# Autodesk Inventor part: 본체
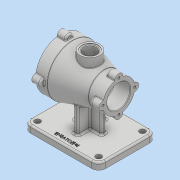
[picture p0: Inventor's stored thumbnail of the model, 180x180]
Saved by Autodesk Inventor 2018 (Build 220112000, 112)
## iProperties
Created: 2020-12
Part Number: 본체
Material: 일반
Document SubType Name: Modeling
Designer: home
Density: 1 g/cm^3
Appearance: 기본값
Author: home
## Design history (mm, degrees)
sketch "스케치1"
  geometry: L1 (-50, 0)-(50, 0); L2 (-50, 0)-(-50, 44); L3 (-50, 44)-(-30, 44); L4 (-30, 44)-(25, 27.5); L5 (25, 27.5)-(50, 27.5); L6 (50, 27.5)-(50, 0); 2 further points
  constraints: 12 end point, 2 perpendicular, 1 coincident, 1 horizontal, 1 midpoint, 1 parallel, 1 vertical
  dimensions: "d0" = 100 distance of L1.start L1.end; "d1" = 88 diameter of L3 L1; "d2" = 55 diameter of L5 L1; "d3" = 20 distance of L2.end L3.end; "d4" = 25 distance of L4.end L5.end
revolve "회전1" sketch "스케치1" stored, may be unused: angle "d5" = 90 deg
node "작업 평면1"
sketch "스케치2"
  geometry: C1 r 17 at (0, 0); 1 further point
  constraints: 1 centre point, 1 coincident
  dimensions: "d7" = 34 diameter of C1
extrude "돌출1" join sketch "스케치2" stored distance "d8" = 10; taper "d9" = 0 deg
node "작업 평면2"
sketch "스케치3"
  geometry: L1 (-65, -50)-(65, -50); L2 (65, -50)-(65, 50); L3 (65, 50)-(-65, 50); L4 (-65, 50)-(-65, -50); L5 (-65, -50)-(65, 50); L6 (65, -50)-(-65, 50); 1 further point
  constraints: 12 end point, 2 midpoint, 2 parallel, 1 horizontal, 1 perpendicular
  dimensions: "d11" = 130 distance of L2.end L3.end; "d12" = 100 distance of L1.end L2.end
extrude "돌출2" join sketch "스케치3" distance "d13" = 12; taper "d14" = 0 deg
sketch "스케치4"
  geometry: L1 (24, 4)-(24, -4); L2 (-24, -4)-(-24, 4); L3 (-4, 25)-(4, 25); L4 (4, -25)-(-4, -25); L5 (-4, -25)-(-4, -4); L6 (-4, 4)-(-4, 25); L7 (4, 25)-(4, 4); L8 (4, -4)-(4, -25); L9 (-24, 4)-(-4, 4); L10 (4, 4)-(24, 4); L11 (24, -4)-(4, -4); L12 (-4, -4)-(-24, -4); 5 further points
  constraints: 24 end point, 10 parallel, 4 perpendicular, 3 horizontal, 2 horizontal alignment, 2 midpoint, 2 vertical alignment
  dimensions: "d15" = 8 distance of L1.start L1.end; "d16" = 8 distance of L3.start L3.end; "d17" = 48 distance of L1.end L2.start; "d18" = 50 distance of L3.end L4.start; "d19" = 20 distance between parallel lines of L7 L1; "d20" = 20 distance between parallel lines of L1 L8; "d21" = 28 distance between parallel lines of L1 L5; "d22" = 48 distance between parallel lines of L1 L2; "d23" = 21 distance between parallel lines of L10 L3; "d24" = 0 distance between parallel lines of L10 L9; "d25" = 8 distance from line of point (0, -4) L10; "d26" = 28 distance from line of point (-4, 0) L1
extrude "돌출3" join sketch "스케치4" stored distance "d27" = 12; taper "d28" = 0 deg
sketch "스케치5"
  geometry: C1 r 44 at (0, 0) reference; C2 r 7 at (44, 0); 2 further points
  constraints: 2 horizontal alignment, 1 centre point, 1 other
  dimensions: "d29" = 14 diameter of C2
extrude "돌출4" join sketch "스케치5" distance "d30" = 15; taper "d31" = 0 deg
sketch "스케치6"
  geometry: C1 r 7 at (-27.5, 0); 2 further points
  constraints: 2 horizontal alignment, 1 centre point, 1 other
  dimensions: "d35" = 14 diameter of C1
extrude "돌출5" join sketch "스케치6" distance "d36" = 15; taper "d37" = 0 deg
sketch "스케치7"
  geometry: L1 (-50, -7)-(-50, 7) reference; L2 (-50, 0)-(-20, 0); L3 (-20, 0)-(-20, 20); L4 (-20, 20)-(-50, 20); L5 (-50, 20)-(-50, 0); L6 (-20, 0)-(27, 0); L7 (27, 0)-(27, 26); L8 (27, 26)-(-20, 26); L9 (-20, 26)-(-20, 0); L10 (50, 43.443)-(50, 6.978) reference; L11 (27, 0)-(50, 0); L12 (50, 0)-(50, 32); L13 (50, 32)-(27, 32); L14 (27, 32)-(27, 0); 3 further points
  constraints: 24 end point, 6 parallel, 3 horizontal, 3 perpendicular, 1 midpoint, 1 point on line
  dimensions: "d41" = 23 distance of L12.end L13.end; "d42" = 64 diameter of L13 L11; "d43" = 52 diameter of L8 L6; "d44" = 40 diameter of L4 L2; "d45" = 30 distance of L3.end L4.end
revolve "회전2" sketch "스케치7" stored, may be unused: angle "d46" = 90 deg
fillet "모깎기1" dims "d47" = 3
fillet "모깎기2" dims "d48" = 3
hole "구멍1" diameter "d51" = 22; stored, may be unused: countersink angle "d55" = 90 deg, drill point angle "d57" = 0 deg; dims "d49" = 10, "d50" = 10, "d52" = 6, "d53" = 28, "d54" = 1, "d56" = 8
chamfer "모따기1" distance "d58" = 1; stored, may be unused: second distance "d59" = 2, angle "d60" = 45 deg
hole "구멍2" diameter "d63" = 4.134; stored, may be unused: countersink angle "d67" = 90 deg, drill point angle "d69" = 118 deg; dims "d64" = 9, "d65" = 28, "d66" = 1, "d68" = 11, "d104" = 10, "d105" = 10
hole "구멍3" diameter "d75" = 4.134; stored, may be unused: countersink angle "d79" = 90 deg, drill point angle "d81" = 118 deg; dims "d76" = 9, "d77" = 28, "d78" = 1, "d80" = 11, "d102" = 10, "d103" = 10
fillet "모깎기3" dims "d85" = 3, "d107" = 1
fillet "모깎기4" dims "d86" = 3
fillet "모깎기5" dims "d87" = 3, "d106" = 1
fillet "모깎기6" dims "d88" = 12
fillet "모깎기7" dims "d89" = 3
node "작업 평면3"
sketch "스케치8"
  geometry: L1 (-53, -50)-(53, -50) reference; 2 further points
  constraints: 1 vertical alignment, 1 other
  dimensions: "d92" = 10 distance from line of L1 point (0, -40)
feature "엠보싱1" sketch "스케치8" dims "d0" = 100, "d1" = 88, "d2" = 55, "d3" = 20, "d4" = 25, "d93" = 0.5, "d94" = 0
sketch "스케치9"
  geometry: A1 r 12 centre (-53, 38) between (-53, 50) and (-65, 38) reference; A2 r 12 centre (53, 38) between (65, 38) and (53, 50) reference; A3 r 12 centre (-53, -38) between (-65, -38) and (-53, -50) reference; A4 r 12 centre (53, -38) between (53, -50) and (65, -38) reference; 5 further points
  constraints: 4 coincident
hole "구멍4" sketch "스케치9" at (-53, 38), (53, 38), (53, -38), (-53, -38) diameter "d95" = 10; stored, may be unused: countersink angle "d99" = 90 deg, drill point angle "d101" = 0 deg; dims "d96" = 10, "d97" = 28, "d98" = 1, "d100" = 11
node "솔리드1"
pattern_circular "원형 패턴1" dims angle "d33" = 360 deg
pattern_circular "원형 패턴2" dims angle "d39" = 360 deg
pattern_circular "원형 패턴3" dims angle "d71" = 360 deg
pattern_circular "원형 패턴4" dims angle "d83" = 360 deg
other parameters: "d6" = 45, "d10" = -82, "d91" = 8.75
